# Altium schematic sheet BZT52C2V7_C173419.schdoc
size 127 x 101 mm
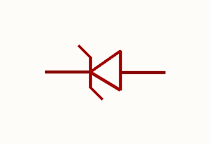
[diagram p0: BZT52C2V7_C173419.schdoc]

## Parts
D?  bzt52c2v7_c173419  [SOD-123_L2.8-W1.8-LS3.7-RD]  (value not drawn)

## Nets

Not connected (* = marked no-connect by the designer): D? 1 2

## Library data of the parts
D? = bzt52c2v7_c173419: 二极管配置:1个独立式;稳压值(标称值):2.7V;稳压值(范围值):2.57V~2.84V;耗散功率(Pd):500mW;; Manufacturer: MDD(辰达半导体); AddInBom: yes; ModelId: 7884390a25fb4c08947731ebfba7e3f8; ModelTransform: 144.8816,62.992,0,0,0,0,0,0,0; Diode Configuration: 1个独立式; Zener Voltage(Nom): 2.7V; Reverse Leakage Current (Ir): 120uA@1V; Pd - Power Dissipation: 500mW; Impedance(Zzt): 110Ω; Tolerance: ±5%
